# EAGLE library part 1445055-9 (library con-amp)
Micro MATE-N-LOK Connectors grid 1.5 mm Source: ENG_CD_1445055_A.pdf
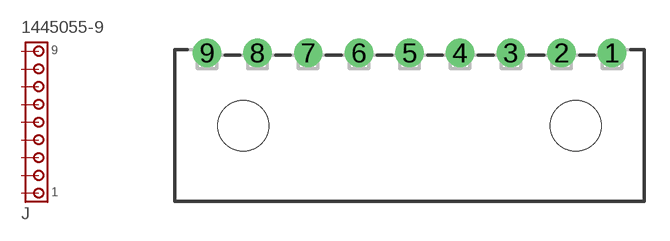
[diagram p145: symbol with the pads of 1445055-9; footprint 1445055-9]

Designator prefix J

## 1445055-9 (MPN: 2-1445055-9; OC_FARNELL: unknown; OC_NEWARK: 17R5938)  [1445055-9]
1  1  pas
2  2  pas
3  3  pas
4  4  pas
5  5  pas
6  6  pas
7  7  pas
8  8  pas
9  9  pas

## Footprint 1445055-9 (pad centres in mm)
Micro MATE-N-LOK Connectors grid 3.0 mm Source: ENG_CD_1445055_A.pdf
drill 1 pad 1.676 round: 1 12,4.32; 2 9,4.32; 3 6,4.32; 4 3,4.32; 5 0,4.32; 6 -3,4.32; 7 -6,4.32; 8 -9,4.32; 9 -12,4.32
hole 3 at -9.85,0
hole 3 at 9.85,0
